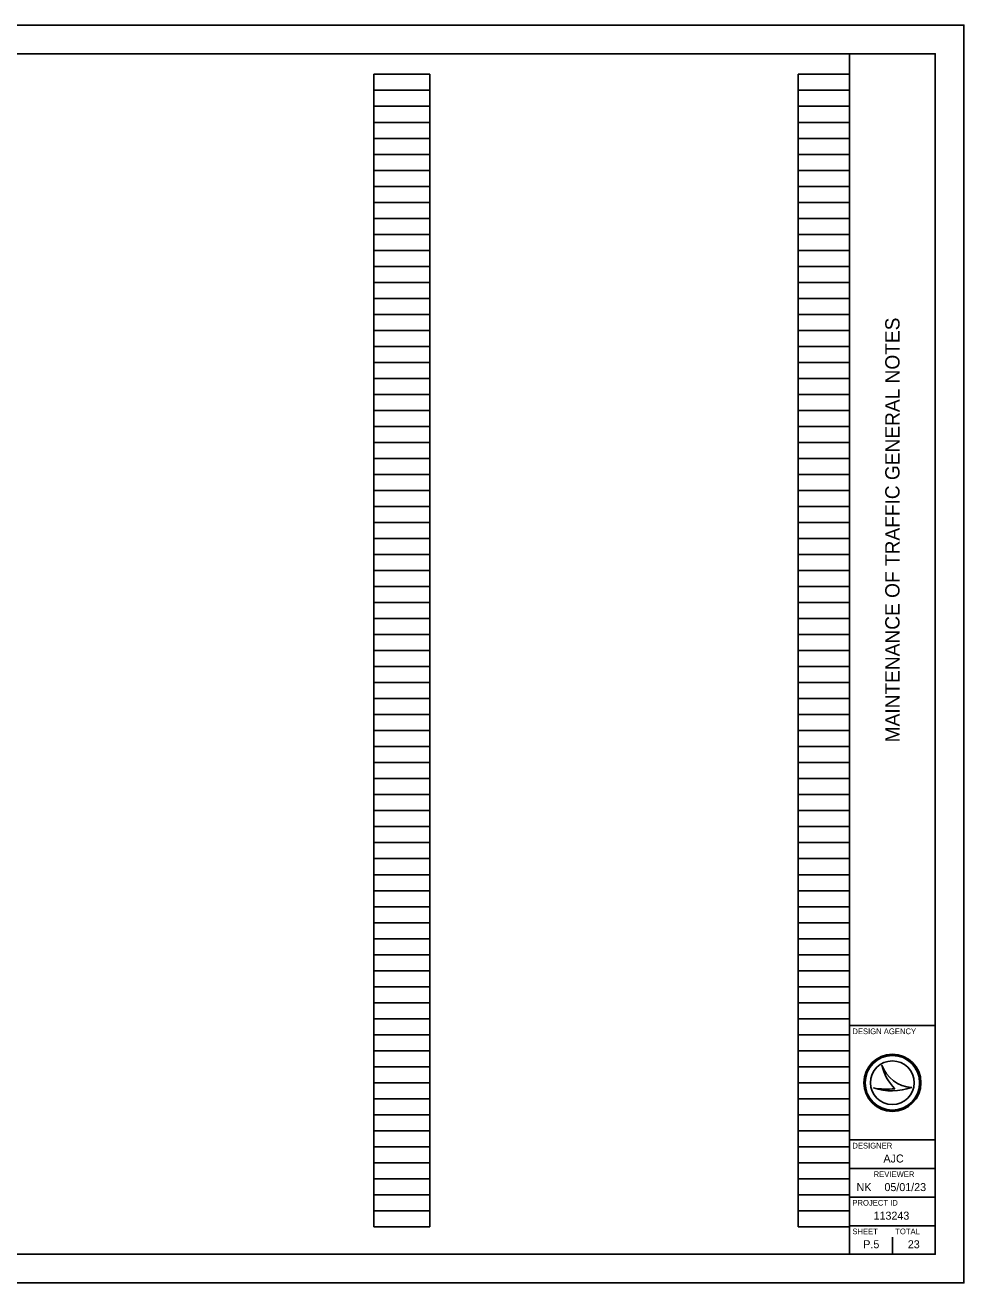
# Model space of a CAD drawing. Extents: x 0 to 34, y 0 to 22.
# Drawn here: x 17.58 to 34, y 0 to 22 of the extents above; entities that cross this region are included whole.
import ezdxf

# ---------------------------------------------------------------- set-up
doc = ezdxf.new("R2010")
doc.units = 0
for name, color, linetype in [('SH_Border', 7, 'Continuous'), ('SH_Cut_Line', 7, 'Continuous'), ('SH_Data', 7, 'Continuous')]:
    doc.layers.add(name, color=color, linetype=linetype)

msp = doc.modelspace()

# ---------------------------------------------------------------- linework, layer by layer
at = {"layer": 'SH_Border'}
for p, q in [((32, 0.5), (32, 21.5)), ((32, 4.5), (33.5, 4.5)), ((32, 2.5), (33.5, 2.5)), ((32, 2), (33.5, 2)), ((32, 1.5), (33.5, 1.5)), ((32, 1), (33.5, 1))]:
    msp.add_line(p, q, dxfattribs=at)
msp.add_lwpolyline([(1.5, 21.5), (33.5, 21.5), (33.5, 0.5), (1.5, 0.5)], close=True, dxfattribs=at)
at = {"layer": 'SH_Cut_Line'}
msp.add_lwpolyline([(0, 0), (34, 0), (34, 22), (0, 22)], close=True, dxfattribs=at)
at = {"layer": 'SH_Data'}
for p, q in [((23.68, 0.98), (23.68, 21.14)), ((23.68, 21.14), (24.66, 21.14)), ((24.66, 0.98), (24.66, 21.14)), ((31.1, 0.98), (31.1, 21.14)), ((31.1, 21.14), (32, 21.14)), ((32, 0.98), (32, 21.14)), ((23.68, 20.86), (24.66, 20.86)), ((31.1, 20.86), (32, 20.86)), ((23.68, 20.58), (24.66, 20.58)), ((31.1, 20.58), (32, 20.58)), ((23.68, 20.3), (24.66, 20.3)), ((31.1, 20.3), (32, 20.3)), ((23.68, 20.02), (24.66, 20.02)), ((31.1, 20.02), (32, 20.02)), ((23.68, 19.74), (24.66, 19.74)), ((31.1, 19.74), (32, 19.74)), ((23.68, 19.46), (24.66, 19.46)), ((31.1, 19.46), (32, 19.46)), ((23.68, 19.18), (24.66, 19.18)), ((31.1, 19.18), (32, 19.18)), ((23.68, 18.9), (24.66, 18.9)), ((31.1, 18.9), (32, 18.9)), ((23.68, 18.62), (24.66, 18.62)), ((31.1, 18.62), (32, 18.62)), ((23.68, 18.34), (24.66, 18.34)), ((31.1, 18.34), (32, 18.34)), ((23.68, 18.06), (24.66, 18.06)), ((31.1, 18.06), (32, 18.06)), ((23.68, 17.78), (24.66, 17.78)), ((31.1, 17.78), (32, 17.78)), ((23.68, 17.5), (24.66, 17.5)), ((31.1, 17.5), (32, 17.5)), ((23.68, 17.22), (24.66, 17.22)), ((31.1, 17.22), (32, 17.22)), ((23.68, 16.94), (24.66, 16.94)), ((31.1, 16.94), (32, 16.94)), ((23.68, 16.66), (24.66, 16.66)), ((31.1, 16.66), (32, 16.66)), ((23.68, 16.38), (24.66, 16.38)), ((31.1, 16.38), (32, 16.38)), ((23.68, 16.1), (24.66, 16.1)), ((31.1, 16.1), (32, 16.1)), ((23.68, 15.82), (24.66, 15.82)), ((31.1, 15.82), (32, 15.82)), ((23.68, 15.54), (24.66, 15.54)), ((31.1, 15.54), (32, 15.54)), ((23.68, 15.26), (24.66, 15.26)), ((31.1, 15.26), (32, 15.26)), ((23.68, 14.98), (24.66, 14.98)), ((31.1, 14.98), (32, 14.98)), ((23.68, 14.7), (24.66, 14.7)), ((31.1, 14.7), (32, 14.7)), ((23.68, 14.42), (24.66, 14.42)), ((31.1, 14.42), (32, 14.42)), ((23.68, 14.14), (24.66, 14.14)), ((31.1, 14.14), (32, 14.14)), ((23.68, 13.86), (24.66, 13.86)), ((31.1, 13.86), (32, 13.86)), ((23.68, 13.58), (24.66, 13.58)), ((31.1, 13.58), (32, 13.58)), ((23.68, 13.3), (24.66, 13.3)), ((31.1, 13.3), (32, 13.3)), ((23.68, 13.02), (24.66, 13.02)), ((31.1, 13.02), (32, 13.02)), ((23.68, 12.74), (24.66, 12.74)), ((31.1, 12.74), (32, 12.74)), ((23.68, 12.46), (24.66, 12.46)), ((31.1, 12.46), (32, 12.46)), ((23.68, 12.18), (24.66, 12.18)), ((31.1, 12.18), (32, 12.18)), ((23.68, 11.9), (24.66, 11.9)), ((31.1, 11.9), (32, 11.9)), ((23.68, 11.62), (24.66, 11.62)), ((31.1, 11.62), (32, 11.62)), ((23.68, 11.34), (24.66, 11.34)), ((31.1, 11.34), (32, 11.34)), ((23.68, 11.06), (24.66, 11.06)), ((31.1, 11.06), (32, 11.06)), ((23.68, 10.78), (24.66, 10.78)), ((31.1, 10.78), (32, 10.78)), ((23.68, 10.5), (24.66, 10.5)), ((31.1, 10.5), (32, 10.5)), ((23.68, 10.22), (24.66, 10.22)), ((31.1, 10.22), (32, 10.22)), ((23.68, 9.94), (24.66, 9.94)), ((31.1, 9.94), (32, 9.94)), ((23.68, 9.66), (24.66, 9.66)), ((31.1, 9.66), (32, 9.66)), ((23.68, 9.38), (24.66, 9.38)), ((31.1, 9.38), (32, 9.38)), ((23.68, 9.1), (24.66, 9.1)), ((31.1, 9.1), (32, 9.1)), ((23.68, 8.82), (24.66, 8.82)), ((31.1, 8.82), (32, 8.82)), ((23.68, 8.54), (24.66, 8.54)), ((31.1, 8.54), (32, 8.54)), ((23.68, 8.26), (24.66, 8.26)), ((31.1, 8.26), (32, 8.26)), ((23.68, 7.98), (24.66, 7.98)), ((31.1, 7.98), (32, 7.98)), ((23.68, 7.7), (24.66, 7.7)), ((31.1, 7.7), (32, 7.7)), ((23.68, 7.42), (24.66, 7.42)), ((31.1, 7.42), (32, 7.42)), ((23.68, 7.14), (24.66, 7.14)), ((31.1, 7.14), (32, 7.14)), ((23.68, 6.86), (24.66, 6.86)), ((31.1, 6.86), (32, 6.86)), ((23.68, 6.58), (24.66, 6.58)), ((31.1, 6.58), (32, 6.58)), ((23.68, 6.3), (24.66, 6.3)), ((31.1, 6.3), (32, 6.3)), ((23.68, 6.02), (24.66, 6.02)), ((31.1, 6.02), (32, 6.02)), ((23.68, 5.74), (24.66, 5.74)), ((31.1, 5.74), (32, 5.74)), ((23.68, 5.46), (24.66, 5.46)), ((31.1, 5.46), (32, 5.46)), ((23.68, 5.18), (24.66, 5.18)), ((31.1, 5.18), (32, 5.18)), ((23.68, 4.9), (24.66, 4.9)), ((31.1, 4.9), (32, 4.9)), ((23.68, 4.62), (24.66, 4.62)), ((31.1, 4.62), (32, 4.62)), ((23.68, 4.34), (24.66, 4.34)), ((31.1, 4.34), (32, 4.34)), ((23.68, 4.06), (24.66, 4.06)), ((31.1, 4.06), (32, 4.06)), ((23.68, 3.78), (24.66, 3.78)), ((31.1, 3.78), (32, 3.78)), ((32.567, 3.81), (32.567, 3.81)), ((23.68, 3.5), (24.66, 3.5)), ((31.1, 3.5), (32, 3.5)), ((32.417, 3.41), (32.417, 3.41)), ((32.75, 3.5), (32.75, 3.5)), ((33.087, 3.419), (33.087, 3.419)), ((23.68, 3.22), (24.66, 3.22)), ((31.1, 3.22), (32, 3.22)), ((23.68, 2.94), (24.66, 2.94)), ((31.1, 2.94), (32, 2.94)), ((23.68, 2.66), (24.66, 2.66)), ((31.1, 2.66), (32, 2.66)), ((23.68, 2.38), (24.66, 2.38)), ((31.1, 2.38), (32, 2.38)), ((23.68, 2.1), (24.66, 2.1)), ((31.1, 2.1), (32, 2.1)), ((23.68, 1.82), (24.66, 1.82)), ((31.1, 1.82), (32, 1.82)), ((23.68, 1.54), (24.66, 1.54)), ((31.1, 1.54), (32, 1.54)), ((23.68, 1.26), (24.66, 1.26)), ((31.1, 1.26), (32, 1.26)), ((23.68, 0.98), (24.66, 0.98)), ((31.1, 0.98), (32, 0.98)), ((32.375, 0.675), (32.375, 0.675)), ((32.75, 0.5), (32.75, 0.8))]:
    msp.add_line(p, q, dxfattribs=at)
for radius in [0.5, 0.477, 0.477, 0.382]:
    msp.add_circle((32.75, 3.5), radius, dxfattribs=at)
for centre, radius, start, end in [((33.116, 3.998), 0.58, 198.9257, 198.9319), ((33.347, 3.97), 0.796, 191.6379, 191.6421), ((33.116, 3.998), 0.58, 198.9319, 267.1657), ((33.347, 3.97), 0.796, 191.6421, 226.0947), ((32.739, 4.37), 1.013, 251.4576, 290.0832), ((32.648, 4.654), 1.266, 259.4964, 259.4995), ((32.739, 4.37), 1.013, 251.4527, 251.4576), ((32.648, 4.654), 1.266, 259.4995, 276.6672)]:
    msp.add_arc(centre, radius, start, end, dxfattribs=at)

# ---------------------------------------------------------------- texts
msp.add_text('MAINTENANCE OF TRAFFIC GENERAL NOTES', height=0.25, rotation=90, dxfattribs=at).set_placement((32.875, 9.455))
for s, height, p in [('DESIGN AGENCY', 0.1, (32.05, 4.35)), ('DESIGNER', 0.1, (32.05, 2.35)), ('AJC', 0.14, (32.594, 2.105)), ('REVIEWER', 0.1, (32.422, 1.85)), ('NK', 0.14, (32.124, 1.605)), ('05/01/23', 0.14, (32.611, 1.605)), ('PROJECT ID', 0.1, (32.05, 1.35)), ('113243', 0.14, (32.421, 1.105)), ('SHEET', 0.1, (32.05, 0.85)), ('TOTAL', 0.1, (32.8, 0.85)), ('P.5', 0.14, (32.241, 0.605)), ('23', 0.14, (33.02, 0.605))]:
    msp.add_text(s, height=height, dxfattribs=at).set_placement(p)

doc.saveas('drawing.dxf')
